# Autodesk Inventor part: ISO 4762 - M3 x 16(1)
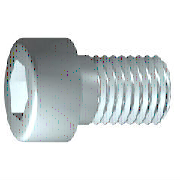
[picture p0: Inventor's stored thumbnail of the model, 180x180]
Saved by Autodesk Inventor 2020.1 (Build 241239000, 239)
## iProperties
Created: 2019-01
Part Number: ISO 4762 - M3 x 16(1)
Material: Edelstahl, 440C
Description: Innensechskantschraube
Document SubType Name: Modeling
Standard: ISO 4762
Designer: lutzd
Standard Revision: Fourth edition 2004-03-01
Standards Organization: ISO
Language: de-DE
Size Designation: M3 x 16
Categories: <MemberInstance><Categories><Category DisplayName="Verbindungselemente" InternalName="e4da775c-781d-43d5-af7c-5136215cf5a6" Mnemonic="FSTN"><Category DisplayNam
Mass: 1.35508 g
Surface Area: 2.58399 cm^2
Volume: 0.174849 cm^3
Density: 7.75 g/cm^3
Appearance: Halbpoliert
IsCustomPart: 0
Author: lutzd
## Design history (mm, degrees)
body "Solid1"
sketch "Skizze1"
  geometry: L1 (-0.867, 0)-(16, 0); L2 (16, 0)-(16, 1.5); L3 (16, 1.5)-(1.25, 1.5); L4 (1.25, 1.5)-(0.943, 1.5); L5 (0.943, 1.5)-(0, 1.5); L6 (0, 1.5)-(0, 2.75); L7 (0, 2.75)-(-3, 2.75); L8 (-3, 2.75)-(-3, 1.443); L9 (-3, 1.443)-(-1.7, 1.443); L10 (-1.7, 1.443)-(-0.867, 0); L11 (-6.8, 0)-(19.8, 0) reference; L12 (0, -0.55)-(0, 3.3) reference; L13 (1.25, 1.5)-(0, 1.5)
  constraints: 22 end point, 6 parallel, 2 collinear, 2 perpendicular, 1 horizontal, 1 point on line
  dimensions: "d1" = 14.75 distance from line of L3.end L2 (= GEL); "d2" = 0.30683 distance of L4.end L3.end (computed from GAL); "d3" = 3 distance between parallel lines of L8 L6 (= KOH); "d4" = 1.3 distance of L8.end L9.end (= INTI); "d5" = 60 deg angle of L10 L1; "d6" = 3 diameter of L3 L1 (= GD); "d7" = 3 diameter of L5 L1 (= BDM); "d8" = 2.88675 diameter of L9 L1 (= 1.1547 x SW); "d9" = 5.5 diameter of L7 L1 (= KOD); "d26" = 16 distance between parallel lines of L12 L2 (= NLG)
workplane "Work Plane1"
fillet "Fillet2" dims "d30" = 0.1 (= R)
revolve "Körper" stored, may be unused: angle "d10" = 90 deg
sketch "Skizze2"
  geometry: L1 (0, -3.85)-(0, 3.85) reference; L2 (-3.85, 0)-(3.85, 0) reference; L3 (1.443, 0)-(0.722, -1.25); L4 (0.722, -1.25)-(-0.722, -1.25); L5 (-0.722, -1.25)-(-1.443, 0); L6 (-1.443, 0)-(-0.722, 1.25); L7 (-0.722, 1.25)-(0.722, 1.25); L8 (0.722, 1.25)-(1.443, 0); 2 further points
  constraints: 12 end point, 1 coincident, 1 horizontal alignment, 1 point on line, 12 other
extrude "Loch" join sketch "Skizze2" stored distance "d11" = 10; taper "d12" = 0 deg
fillet "Rundung1" dims "d17" = 0.3 (= RR)
feature "Gewinde" dims "d13" = 14.75 (= GEL), "d14" = 0
chamfer "Fase1" distance "d15" = 0.30673 (= -0.5 x SPD + 0.5 x GD); stored, may be unused: second distance "d16" = 0.30673 (= GUL), angle "d27" = 45 deg
other parameters: "GD" = 3 [user parameter; used in 2 equation terms], "NLG" = 16 [user parameter; used in 1 equation term], "GEL" = 14.75 [user parameter; used in 2 equation terms], "KOD" = 5.5 [user parameter; used in 1 equation term], "KOH" = 3 [user parameter; used in 1 equation term], "INTI" = 1.3 [user parameter; used in 1 equation term], "GAL" = 0.30673 (= 0.61345 x PTC) [user parameter; used in 1 equation term], "GUL" = 0.30673 (= 0.61345 x PTC) [user parameter; used in 1 equation term], "BDM" = 3 (= NND) [user parameter; used in 1 equation term], "SW" = 2.5 [user parameter; used in 2 equation terms], "RR" = 0.3 [user parameter; used in 1 equation term], "SPD" = 2.38655 (= NND - 1.2269 x PTC) [user parameter; used in 1 equation term], "d19" = 0, "d28" = 0, "d29" = 0, "R" = 0.1 [user parameter; used in 1 equation term], "TOA" = 30 deg [user parameter], "GD1" = 2.38655 (= THREADDIA - 1.2269 x PTC) [user parameter], "THREADDIA" = 3 [user parameter; used in 1 equation term], "FAWI" = 45 deg [user parameter], "PTC" = 0.5 [user parameter; used in 5 equation terms], "NND" = 3 [user parameter; used in 2 equation terms], "E0" = 2.8875 (= 1.155 x SW) [user parameter]
